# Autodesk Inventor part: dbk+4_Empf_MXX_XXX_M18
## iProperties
Shininess: 20.0
Length Units: 11269
Angle Units: 11279
Time Units: 11290
Mass Units: 11283
Length Display Precision: 2
Angle Display Precision: 2
Part Number: dbk+4_Empf_MXX_XXX_M18
Material: Nichtrostender Stahl - 440C
Document SubType Name: Modellieren
Description: Ipc-25 /CXX/M18
Checked By: Alves
Created: 2005-08
Designer: Ohle
Manufacturer: Standard
Standards Organization: Custom
Density: 0.0
Volumn: 0.0
Area: 0.0
PropertySet Name: Model Information
Control State: 0
Master: False
Checked Out: False
BESTELLNUMMER: Ipc-25 /CXX/M18
ME: ST
Title: Ipc Sensoren
Author: Ohle
Comments: keine Bemerkung
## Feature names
1. Grundkörper pico+ [Revolution]
2. Flächenverjüngung1
3. Extrusion10
4. Rundung3 [Fillet]
5. Extrusion11
6. Kabelauslass [Extrusion]
